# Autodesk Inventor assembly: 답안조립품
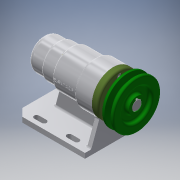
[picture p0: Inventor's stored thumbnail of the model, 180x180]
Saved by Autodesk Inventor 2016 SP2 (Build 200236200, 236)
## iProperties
Created: 2017-09
Part Number: 답안조립품
Document SubType Name: Assembly
Designer: Administrator
Author: Administrator
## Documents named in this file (12)
- D:\470907V1010\답안조립품.iam
- D:\470907V1010\본체.ipt
- D:\470907V1010\커버.ipt
- D:\470907V1010\볼트 M4 x 12.ipt
- D:\470907V1010\축.ipt
- D:\470907V1010\키 5 x 5 x 16.ipt
- D:\470907V1010\베어링 6004.ipt
- D:\470907V1010\오일 실 20x35x7.ipt
- D:\470907V1010\V벨트풀리.ipt
- D:\470907V1010\멈춤나사 M3x8.ipt
- D:\470907V1010\어댑터슬리브.ipt
- D:\470907V1010\베어링 51202.ipt
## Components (1 placed, 1 different names)
1. V벨트풀리:1
